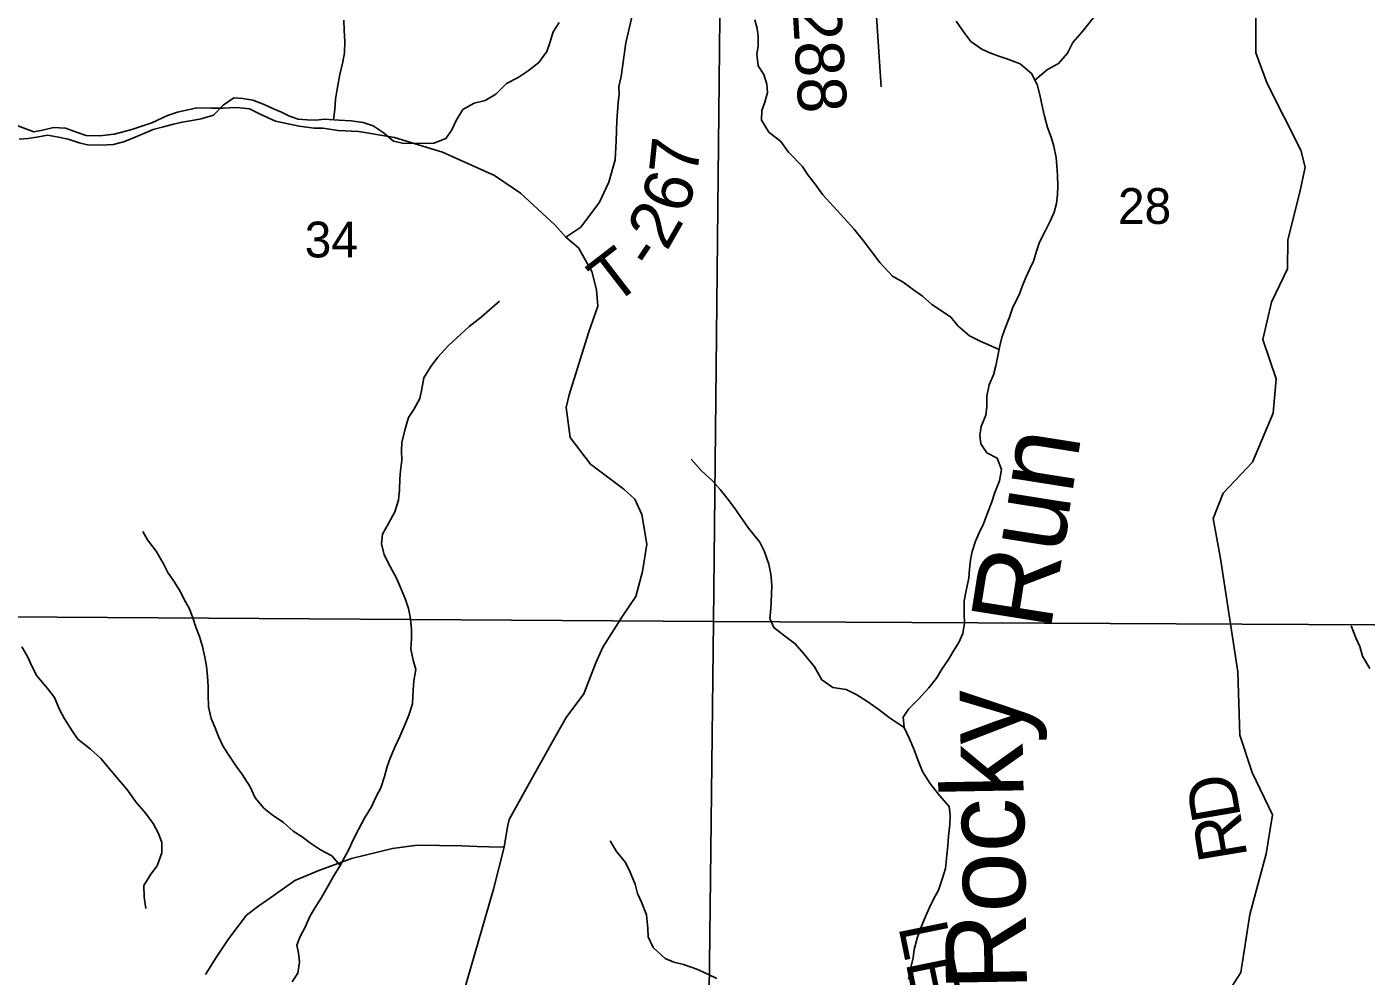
# Model space of a CAD drawing. Extents: x 2043100 to 2470832, y 443715 to 810583.
# Drawn here: x 2291305 to 2299570, y 601016 to 606876 of the extents above; entities that cross this region are included whole.
import ezdxf

# ---------------------------------------------------------------- set-up
doc = ezdxf.new("R2010")
doc.units = 0
for name, color, linetype in [('GM_X_County_Road', 7, 'Continuous'), ('GM_X_Minor_River', 7, 'Continuous'), ('GM_X_Minor_River_Text', 7, 'Continuous'), ('GM_X_Section', 7, 'Continuous'), ('GM_X_Section_Text', 7, 'Continuous'), ('GM_X_Township_Road', 7, 'Continuous'), ('GM_X_Township_Road_Text', 7, 'Continuous'), ('GM_X_Township_ROW', 7, 'Continuous')]:
    doc.layers.add(name, color=color, linetype=linetype)

msp = doc.modelspace()

# ---------------------------------------------------------------- linework, layer by layer
at = {"layer": 'GM_X_County_Road'}
msp.add_lwpolyline([(2291250.1, 606264), (2291347.8, 606227.6), (2291401.7, 606238.1), (2291469.5, 606254.8), (2291543.6, 606249.5), (2291611.8, 606226), (2291672.1, 606204.6), (2291756.1, 606203.3), (2291844, 606214.1), (2291953.7, 606241.2), (2292077.3, 606282.4), (2292172.9, 606329.3), (2292234.7, 606349.9), (2292354.4, 606375.1), (2292442.4, 606373.9), (2292514.4, 606374.5), (2292600.4, 606377.3), (2292678.5, 606370), (2292744.8, 606336.6), (2292839.3, 606293.4), (2292985.6, 606262.6), (2293077.7, 606249.5), (2293131.7, 606249.9), (2293225.9, 606236.8), (2293353.9, 606229.9), (2293574.3, 606191.9), (2293871.2, 606102.4), (2294190.7, 605959.1), (2294351.8, 605848.4), (2294563.7, 605654), (2294630.5, 605578.4), (2294709.1, 605511.1), (2294792.6, 605365.6), (2294821.7, 605251.6), (2294828.7, 605151.5), (2294772.3, 604986.7), (2294652.1, 604605), (2294632.9, 604526.7), (2294658.7, 604340.6), (2294784.3, 604177.5), (2294989.8, 604023.1), (2295056.5, 603959.6), (2295101.4, 603865.8), (2295131.2, 603683.8), (2295104.9, 603513.2), (2295062.4, 603360.6), (2294981.6, 603237.7), (2294859.5, 603046.2), (2294816.4, 602949.7), (2294742.3, 602758.7), (2294633.7, 602613.4), (2294545.3, 602456.4), (2294417.5, 602228.8), (2294281.9, 601983.1), (2294272.4, 601939), (2294250.7, 601813.4), (2294184.2, 601554), (2294000.5, 600912.8)], dxfattribs=at)
at = {"layer": 'GM_X_Minor_River'}
for points in [[(2297526.1, 606546.7), (2297602.8, 606612.8), (2297672.5, 606649.3), (2297728, 606713.8), (2297759.5, 606780.1), (2297817, 606844.5), (2297866.5, 606906.9), (2297924, 606977.4), (2297987.5, 607035.9), (2298043.2, 607080.3), (2298114.6, 607148.8), (2298146.2, 607209.1), (2298207.6, 607275.6), (2298271.3, 607312), (2298347, 607352.6), (2298398.8, 607372.9), (2298472.3, 607433.5), (2298527.8, 607493.9)], [(2291257.5, 606181.5), (2291311.4, 606185.9), (2291367.3, 606194.2), (2291433.2, 606206.7), (2291501.2, 606195.1), (2291561.2, 606181.5), (2291629.3, 606159.9), (2291679.4, 606148.2), (2291761.3, 606144.7), (2291841.2, 606149.2), (2291903, 606165.6), (2291958.8, 606188), (2292084.3, 606242.9), (2292148.2, 606259.3), (2292210, 606275.8), (2292263.8, 606288.1), (2292325.7, 606298.5), (2292381.6, 606308.9), (2292457.4, 606331.4), (2292516.9, 606391.9), (2292582.5, 606438.4), (2292638.5, 606432.7), (2292700.5, 606423.1), (2292770.6, 606395.5), (2292826.8, 606369.8), (2292876.9, 606350.1), (2292927, 606324.4), (2292979.1, 606306.7), (2293035.1, 606301.1), (2293089, 606299.4), (2293142.9, 606305.8), (2293230.9, 606300.3), (2293306.9, 606294.8), (2293380.9, 606285.3), (2293442.9, 606265.7), (2293505.2, 606224), (2293567.5, 606170.3), (2293633.5, 606156.8), (2293691.5, 606157.1), (2293765.4, 606155.6), (2293817.4, 606157.9), (2293891.1, 606186.4), (2293926.7, 606236.7), (2293954.3, 606297), (2293995.8, 606365.3), (2294065.4, 606403.8), (2294133.3, 606420.3), (2294198.9, 606460.8), (2294264.4, 606525.3), (2294338.1, 606563.8), (2294399.7, 606604.2), (2294465.3, 606656.7), (2294514.8, 606723.2), (2294532.4, 606777.3), (2294553.9, 606845.6), (2294589.5, 606901.9)], [(2293197.8, 606302.4), (2293206.5, 606366.3), (2293210, 606428.4), (2293223.5, 606502.6), (2293236.9, 606580.8), (2293254.4, 606659), (2293266, 606715.1), (2293267.5, 606785.2), (2293263, 606855.3), (2293262.6, 606917.3)], [(2297304.8, 604884.2), (2297188.9, 604936), (2297122.7, 604969.6), (2297050.4, 605031.2), (2297008.1, 605083), (2296955.9, 605118.8), (2296889.6, 605162.4), (2296831.3, 605214.1), (2296769, 605259.7), (2296712.8, 605299.4), (2296646.6, 605337), (2296568.1, 605420.7), (2296511.6, 605496.4), (2296469.2, 605554.2), (2296408.8, 605629.9), (2296348.4, 605695.6), (2296281.9, 605769.3), (2296217.5, 605838.9), (2296169, 605904.7), (2296124.7, 605962.5), (2296090.3, 606016.3), (2296005.8, 606101.9), (2295957.4, 606167.7), (2295885.1, 606225.3), (2295838.6, 606299.1), (2295840.2, 606359.2), (2295859.8, 606411.4), (2295875.4, 606469.6), (2295871, 606521.6), (2295852.6, 606581.6), (2295818.2, 606635.4), (2295809.7, 606707.4), (2295817.4, 606759.6), (2295819, 606815.7), (2295812.6, 606865.7), (2295798.3, 606919.7)], [(2296720, 602552), (2296713.6, 602614), (2296745.2, 602664.3), (2296806.7, 602726.8), (2296872.2, 602795.3), (2296919.7, 602855.7), (2296951.3, 602911.9), (2296992.9, 602970.3), (2297020.5, 603020.5), (2297056.1, 603076.8), (2297081.7, 603131), (2297091.2, 603195.2), (2297088.8, 603255.3), (2297090.2, 603333.4), (2297101.8, 603397.5), (2297117.2, 603473.7), (2297122.9, 603527.8), (2297128.4, 603585.9), (2297138.1, 603638), (2297159.6, 603702.3), (2297181.2, 603752.5), (2297208.8, 603808.7), (2297236.3, 603881), (2297257.9, 603937.2), (2297279.4, 604001.4), (2297306.9, 604073.7), (2297320.4, 604143.9), (2297293.9, 604213.8), (2297229.7, 604247.4), (2297191.4, 604301.2), (2297187, 604355.3), (2297194.6, 604409.4), (2297224.1, 604479.7), (2297229.7, 604529.8), (2297229.3, 604595.8), (2297242.8, 604666), (2297270.3, 604728.3), (2297283.9, 604784.4), (2297297.5, 604844.6), (2297309, 604906.8), (2297322.7, 604958.9), (2297342.2, 605015.1), (2297369.7, 605083.4), (2297389.3, 605145.6), (2297428.7, 605221.9), (2297448.3, 605274.1), (2297469.9, 605328.3), (2297491.6, 605378.5), (2297517.2, 605428.8), (2297538.7, 605497), (2297554.3, 605547.1), (2297589.8, 605615.4), (2297619.4, 605675.7), (2297644.9, 605732), (2297658.6, 605786.1), (2297666.2, 605840.2), (2297667.8, 605892.3), (2297665.3, 605960.4), (2297660.9, 606018.4), (2297656.6, 606068.5), (2297642.1, 606138.5), (2297625.7, 606194.4), (2297603.3, 606254.4), (2297584.8, 606324.3), (2297572.5, 606378.3), (2297555.9, 606456.3), (2297539.5, 606520.3), (2297505.1, 606588.2), (2297434.7, 606647.8), (2297358.6, 606675.3), (2297302.5, 606695), (2297248.4, 606714.7), (2297198.3, 606738.4), (2297130, 606786), (2297087.7, 606843.8), (2297039.2, 606911.6)], [(2292942.4, 600981.8), (2292978, 601034.1), (2292987.5, 601102.3), (2292981.1, 601158.3), (2292970.8, 601208.3), (2292992.4, 601260.5), (2293020, 601314.7), (2293053.5, 601389), (2293085.1, 601439.3), (2293124.6, 601501.6), (2293164.1, 601574), (2293195.7, 601630.3), (2293239.1, 601698.6), (2293264.8, 601748.8), (2293294.4, 601803.1), (2293318, 601853.3), (2293351.5, 601921.6), (2293388.9, 601991.9), (2293432.4, 602062.3), (2293462, 602124.6), (2293489.5, 602178.8), (2293513, 602249.1), (2293528.6, 602311.2), (2293548.2, 602361.4), (2293575.7, 602429.7), (2293607.2, 602496), (2293638.7, 602568.3), (2293662.3, 602626.5), (2293685.7, 602696.7), (2293689.1, 602780.8), (2293692.7, 602838.9), (2293706.2, 602909.1), (2293689.8, 602967.1), (2293675.4, 603035.1), (2293678.9, 603101.2), (2293678.5, 603157.2), (2293670, 603233.3), (2293659.6, 603285.3), (2293641.3, 603341.2), (2293616.9, 603401.2), (2293586.4, 603473.1), (2293547.9, 603544.9), (2293511.4, 603616.8), (2293493, 603684.7), (2293500.6, 603744.8), (2293538.1, 603811.2), (2293575.5, 603881.5), (2293599, 603953.7), (2293604.6, 604017.8), (2293608.1, 604086), (2293611.7, 604136), (2293619.3, 604202.2), (2293616.9, 604258.2), (2293620.5, 604310.3), (2293639.9, 604394.5), (2293661.4, 604464.8), (2293693, 604515), (2293730.5, 604581.4), (2293742.1, 604641.5), (2293755.6, 604709.7), (2293799, 604780.1), (2293842.6, 604836.4), (2293908, 604908.9), (2293981.5, 604977.5), (2294035.1, 605025.9), (2294108.6, 605084.4), (2294160.3, 605128.8), (2294221.8, 605183.3)], [(2296720, 602552), (2296635.7, 602607.5), (2296557.4, 602667.1), (2296483.1, 602718.7), (2296426.9, 602752.4), (2296360.7, 602786), (2296278.7, 602797.5), (2296210.4, 602845.1), (2296165.9, 602924.9), (2296101.4, 603004.6), (2296047, 603068.3), (2295980.8, 603116), (2295914.4, 603167.6), (2295890.1, 603223.5), (2295895.7, 603283.6), (2295901, 603371.8), (2295902.6, 603429.9), (2295896.1, 603497.9), (2295883.7, 603559.9), (2295855.2, 603641.8), (2295828.8, 603695.7), (2295758.3, 603781.4), (2295669.5, 603909), (2295625.1, 603968.8), (2295582.8, 604020.5), (2295536.4, 604074.3), (2295466.1, 604138), (2295405.6, 604207.7)], [(2293239.9, 601700.2), (2293186.8, 601758.4), (2293116.6, 601795.9), (2293056.3, 601837.6), (2293004.1, 601877.3), (2292949.9, 601911), (2292889.6, 601964.7), (2292819.3, 602012.3), (2292767.1, 602054), (2292714.7, 602117.8), (2292684.2, 602185.7), (2292635.7, 602259.4), (2292597.4, 602313.3), (2292546.9, 602387), (2292514.6, 602438.9), (2292488.2, 602494.8), (2292467.9, 602548.7), (2292443.5, 602606.6), (2292427, 602678.6), (2292424.5, 602752.7), (2292424.1, 602804.8), (2292419.7, 602866.8), (2292413.3, 602928.8), (2292404.9, 602984.9), (2292390.4, 603050.8), (2292370, 603112.8), (2292347.6, 603170.7), (2292329.2, 603228.7), (2292308.9, 603284.6), (2292276.5, 603340.5), (2292252.1, 603392.4), (2292211.8, 603454.2), (2292175.4, 603508), (2292147, 603565.9), (2292104.5, 603639.8), (2292050.1, 603709.5), (2292021.8, 603761.4)], [(2299593, 602914.8), (2299546.5, 602990.6), (2299530.1, 603050.6), (2299505.7, 603104.5), (2299477.2, 603178.4)], [(2291275.4, 603049.7), (2291309.8, 602989.8), (2291338.2, 602925.9), (2291366.6, 602870), (2291435.1, 602790.4), (2291475.4, 602736.6), (2291510, 602658.7), (2291538.3, 602604.8), (2291584.8, 602531), (2291621.1, 602479.2), (2291697.5, 602417.6), (2291761.8, 602360), (2291826.3, 602284.3), (2291882.7, 602216.6), (2291929.1, 602162.8), (2291975.5, 602095), (2292039.9, 602021.3), (2292084.3, 601959.5), (2292118.7, 601897.7), (2292139.1, 601841.7), (2292137.6, 601777.6), (2292110.2, 601697.4), (2292070.6, 601645), (2292027.1, 601576.7), (2292029.6, 601504.6), (2292040.1, 601434.6)], [(2296746.9, 600998.3), (2296760.4, 601070.4), (2296774, 601130.6), (2296781.6, 601180.7), (2296799.1, 601250.9), (2296822.6, 601315.1), (2296850.1, 601385.4), (2296875.7, 601439.6), (2296901.3, 601495.9), (2296930.9, 601548.1), (2296954.4, 601614.3), (2296973.9, 601680.6), (2296983.3, 601762.7), (2296988.9, 601820.8), (2296992.5, 601880.9), (2297000, 601953.1), (2297003.6, 602007.2), (2296997.2, 602063.2), (2296936.8, 602130.9), (2296878.3, 602208.6), (2296831.8, 602280.4), (2296803.4, 602352.3), (2296781, 602414.2), (2296752.5, 602482.1), (2296720, 602552)], [(2295563.9, 601002.7), (2295507.8, 601028.3), (2295439.6, 601059.9), (2295357.5, 601087.5), (2295297.5, 601103.1), (2295243.4, 601124.8), (2295171, 601192.4), (2295140.5, 601258.3), (2295138.2, 601310.3), (2295129.6, 601394.4), (2295099.1, 601472.3), (2295074.7, 601526.2), (2295058.3, 601584.2), (2295025.8, 601662), (2294999.4, 601717.9), (2294945, 601785.7), (2294904.6, 601851.5)]]:
    msp.add_lwpolyline(points, dxfattribs=at)
at = {"layer": 'GM_X_Section'}
for points in [[(2290881.7, 608528.4), (2295598, 608504.4), (2295541.7, 603205.3), (2290867.3, 603235.9), (2290875.5, 606259.3)], [(2295598, 608504.4), (2300874.8, 608467.8), (2300844.4, 603179.1), (2295541.7, 603205.3)], [(2295541.7, 603205.3), (2295481.1, 597922.3), (2290850.4, 597973.4), (2290860.2, 600886.8), (2290867.3, 603235.9)], [(2300844.4, 603179.1), (2300812.2, 597864.3), (2295481.1, 597922.3), (2295541.7, 603205.3)]]:
    msp.add_lwpolyline(points, close=True, dxfattribs=at)
at = {"layer": 'GM_X_Township_Road'}
for points in [[(2296576.8, 606505.1), (2296525.7, 607284)], [(2298647.9, 600808.9), (2298795.6, 601038.6), (2298852.1, 601397.7), (2298952.4, 601771.3), (2298992, 602012), (2298865.5, 602273.3), (2298791.2, 602503.1), (2298777.3, 602895.6), (2298670.4, 603593.8), (2298625.9, 603841.8), (2298688.4, 603996.7), (2298868.5, 604188.6), (2298995.6, 604492.3), (2299015.5, 604702.9), (2298933.1, 604946.5), (2298984.8, 605177.4), (2299084.8, 605382.7), (2299087, 605561), (2299160.1, 605856.2), (2299192.6, 606008.7), (2299167.6, 606114.7), (2298959.5, 606525.5), (2298889.6, 606715.2), (2298890.8, 607202.1)], [(2294630.5, 605578.4), (2294723.9, 605639.4), (2294838.4, 605794.7), (2294897.1, 605917.5), (2294935.8, 606054.1), (2294942.6, 606172.3), (2294945.4, 606298.6), (2294954.3, 606408.8), (2294959.8, 606461), (2294959.3, 606507.1), (2294972.7, 606569.3), (2295002.7, 606777.9), (2295039.1, 606934.5), (2295071.9, 607059.1)], [(2294155.7, 601815.6), (2294155.9, 601815.6), (2294250.7, 601813.4)]]:
    msp.add_lwpolyline(points, dxfattribs=at)
at = {"layer": 'GM_X_Township_ROW'}
msp.add_lwpolyline([(2292408.9, 601027.3), (2292474.4, 601132.1), (2292552.9, 601249.9), (2292609.7, 601324.1), (2292662, 601393.9), (2292736.2, 601450.6), (2292832.2, 601516.1), (2292958.8, 601607.7), (2293107.2, 601668.8), (2293307.9, 601743), (2293561.1, 601804.1), (2293713.8, 601825.9), (2293988.8, 601821.6), (2294084.8, 601817.2), (2294155.7, 601815.6)], dxfattribs=at)

# ---------------------------------------------------------------- texts
at = {"layer": 'GM_X_Minor_River_Text'}
for s, height, rotation, p in [('Run', 499.94, 81.00647, (2297620.8, 603139.4)), ('Rocky', 499.93, 91.00766, (2297477.7, 600929.9))]:
    msp.add_text(s, height=height, rotation=rotation, dxfattribs=at).set_placement(p)
at = {"layer": 'GM_X_Section_Text'}
for s, p in [('28', (2298038.4, 605659.5)), ('34', (2293020.2, 605452.7))]:
    msp.add_text(s, height=220.83, rotation=0.00001, dxfattribs=at).set_placement(p)
at = {"layer": 'GM_X_Township_Road_Text'}
for s, rotation, p in [('T-288', 273.36678, (2296007.2, 607382.5)), ('7', 84.0996, (2295442, 605951.6)), ('6', 72.72369, (2295374.1, 605711.7)), ('2', 60.30192, (2295254.3, 605486.2)), ('T', 37.68591, (2294924.1, 605149.8)), ('-', 56.21363, (2295173.5, 605364)), ('D', 99.78001, (2298797.9, 601998.4)), ('R', 99.45656, (2298838.7, 601753.5)), ('L', 281.56377, (2296682.5, 601322.1)), ('E', 281.56377, (2296727.5, 601102.3))]:
    msp.add_text(s, height=300, rotation=rotation, dxfattribs=at).set_placement(p)

doc.saveas('drawing.dxf')
